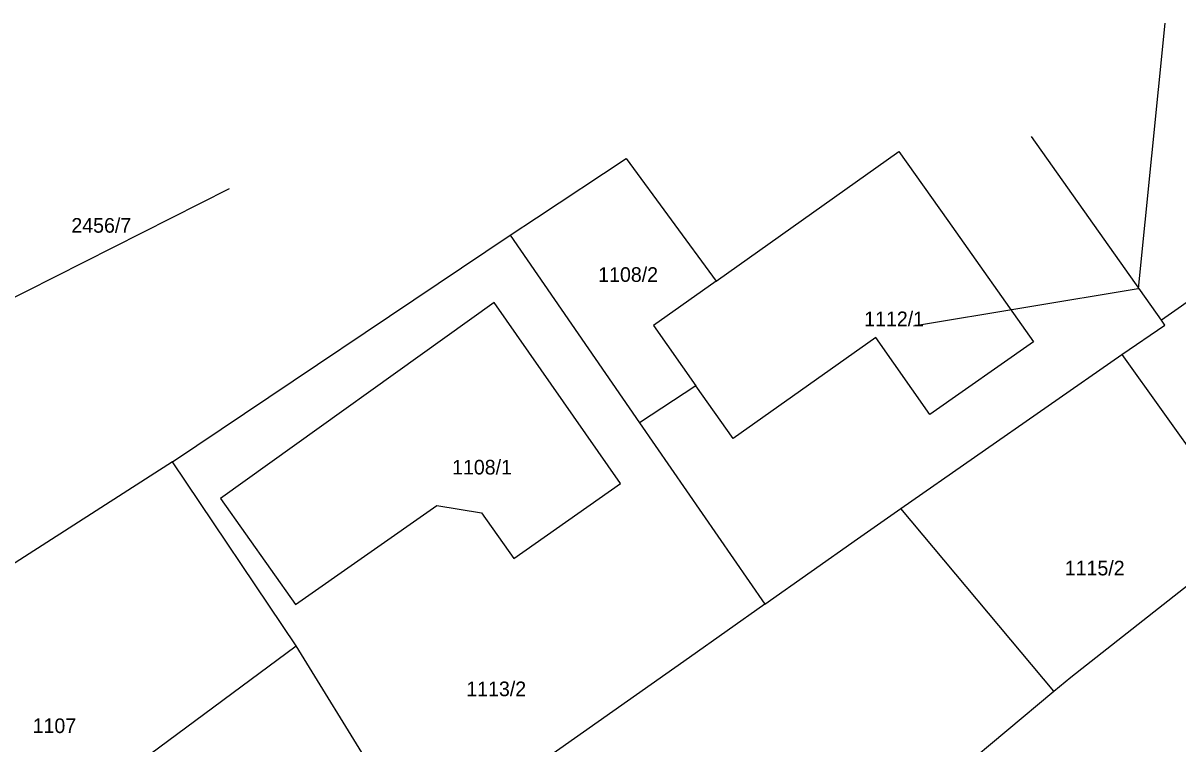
# Model space of a CAD drawing. Extents: x -601580 to 4, y -1204314 to 4.
# Drawn here: x -599865.7 to -599806.5, y -1203262.9 to -1203226 of the extents above; entities that cross this region are included whole.
import ezdxf

# ---------------------------------------------------------------- set-up
doc = ezdxf.new("R2010")
doc.units = 0
for name, color, linetype in [('00-KN-HRANICE PARCEL', 7, 'Continuous'), ('00-KN-PARC. CISLA', 7, 'Continuous'), ('00-SITE KOM. KABEL', 7, 'Continuous')]:
    doc.layers.add(name, color=color, linetype=linetype)

msp = doc.modelspace()

# ---------------------------------------------------------------- linework, layer by layer
at = {"layer": '00-KN-HRANICE PARCEL'}
for p, q in [((-599807.32, -1203241.23), (-599813.98, -1203231.81)), ((-599834.75, -1203232.93), (-599830.15, -1203239.23)), ((-599892.75, -1203253.5), (-599855.08, -1203234.47)), ((-599799.73, -1203235.84), (-599807.32, -1203241.23)), ((-599858, -1203248.48), (-599840.71, -1203236.87)), ((-599840.71, -1203236.87), (-599834.07, -1203246.48)), ((-599820.68, -1203250.87), (-599809.35, -1203242.99)), ((-599809.35, -1203242.99), (-599802.74, -1203252.25)), ((-599831.18, -1203244.58), (-599834.07, -1203246.48)), ((-599834.07, -1203246.48), (-599827.65, -1203255.77)), ((-599858, -1203248.48), (-599875.09, -1203259.44)), ((-599851.67, -1203257.91), (-599858, -1203248.48)), ((-599812.84, -1203260.24), (-599820.68, -1203250.87)), ((-599859.18, -1203263.48), (-599851.67, -1203257.91)), ((-599845.23, -1203268.36), (-599851.67, -1203257.91)), ((-599831.26, -1203275.61), (-599812.84, -1203260.24))]:
    msp.add_line(p, q, dxfattribs=at)
for points in [[(-599830.15, -1203239.23), (-599820.78, -1203232.58), (-599818.28, -1203236.12), (-599813.89, -1203242.33), (-599819.2, -1203246.05), (-599821.96, -1203242.11), (-599829.28, -1203247.28), (-599831.18, -1203244.58)], [(-599840.71, -1203236.87), (-599839.35, -1203235.98), (-599834.75, -1203232.93)], [(-599830.15, -1203239.23), (-599833.35, -1203241.5), (-599831.18, -1203244.58)], [(-599842.18, -1203251.1), (-599840.52, -1203253.44), (-599835.04, -1203249.59), (-599841.53, -1203240.32), (-599855.54, -1203250.36), (-599851.71, -1203255.8), (-599844.46, -1203250.72), (-599842.18, -1203251.1)], [(-599809.35, -1203242.99), (-599807.15, -1203241.47), (-599807.32, -1203241.23)], [(-599827.65, -1203255.77), (-599822.91, -1203252.42), (-599820.68, -1203250.87)], [(-599812.84, -1203260.24), (-599811.97, -1203259.51), (-599802.74, -1203252.25)], [(-599827.65, -1203255.77), (-599831.51, -1203258.5), (-599840.12, -1203264.57)]]:
    msp.add_lwpolyline(points, dxfattribs=at)
at = {"layer": '00-SITE KOM. KABEL'}
for points in [[(-599807.16, -1203226), (-599808.52, -1203239.606)], [(-599820.026, -1203241.505), (-599808.52, -1203239.606)]]:
    msp.add_lwpolyline(points, dxfattribs=at)

# ---------------------------------------------------------------- texts
at = {"layer": '00-KN-PARC. CISLA'}
for s, p in [('2456/7', (-599863.191, -1203236.74)), ('1108/2', (-599836.191, -1203239.26)), ('1112/1', (-599822.559, -1203241.53)), ('1108/1', (-599843.679, -1203249.13)), ('1115/2', (-599812.281, -1203254.3)), ('1113/2', (-599842.951, -1203260.49)), ('1107', (-599865.175, -1203262.38))]:
    msp.add_text(s, height=0.75, dxfattribs=at).set_placement(p)

doc.saveas('drawing.dxf')
